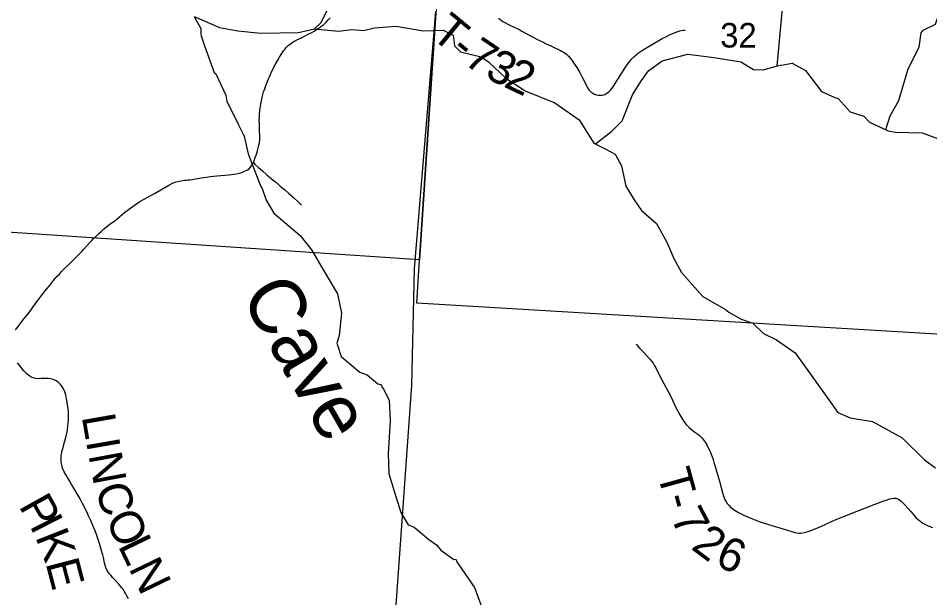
# Model space of a CAD drawing. Extents: x 396.2 to 468.4, y 232.6 to 279.1.
# Drawn here: x 414.633 to 416.187, y 271.056 to 272.044 of the extents above; entities that cross this region are included whole.
import ezdxf

# ---------------------------------------------------------------- set-up
doc = ezdxf.new("R2010")
doc.units = 0
for name, color, linetype in [('Default', 7, 'Continuous'), ('GM_X_County_Road', 7, 'Continuous'), ('GM_X_County_Road_Text', 7, 'Continuous'), ('GM_X_Minor_River', 7, 'Continuous'), ('GM_X_Minor_River_Text', 7, 'Continuous'), ('GM_X_Section', 7, 'Continuous'), ('GM_X_Section_Text', 7, 'Continuous'), ('GM_X_Township', 7, 'Continuous'), ('GM_X_Township_Road', 7, 'Continuous'), ('GM_X_Township_Road_Text', 7, 'Continuous')]:
    doc.layers.add(name, color=color, linetype=linetype)

msp = doc.modelspace()

# ---------------------------------------------------------------- linework, layer by layer
at = {"layer": 'Default'}
msp.add_lwpolyline([(414.466, 270.6401), (415.2492, 270.5871), (415.2566, 270.6906), (415.256, 270.6948), (415.2559, 270.6981), (415.2559, 270.7015), (415.2563, 270.7076), (415.2611, 270.7635), (415.2633, 270.7866), (415.2638, 270.7932), (415.2639, 270.7959), (415.264, 270.7987), (415.2639, 270.801), (415.2637, 270.8037), (415.2633, 270.8055), (415.2628, 270.8077), (415.262, 270.81), (415.2608, 270.8124), (415.3044, 271.4185), (415.3087, 271.617), (415.3585, 272.2209)], dxfattribs=at)
at = {"layer": 'GM_X_County_Road'}
for points in [[(414.6286, 271.5128), (414.6333, 271.519), (414.6378, 271.5247), (414.6434, 271.532), (414.6498, 271.5402), (414.6562, 271.5486), (414.6637, 271.5593), (414.6699, 271.5674), (414.6751, 271.5743), (414.6789, 271.5792), (414.6825, 271.5836), (414.6862, 271.5881), (414.6898, 271.5926), (414.6935, 271.597), (414.6967, 271.6007), (414.6996, 271.6041), (414.7032, 271.608), (414.7071, 271.6123), (414.7128, 271.6179), (414.7176, 271.6228), (414.7232, 271.6283), (414.7292, 271.6341), (414.7356, 271.6406), (414.7409, 271.6461), (414.745, 271.6506), (414.7493, 271.6553), (414.7551, 271.6618), (414.7585, 271.6653), (414.7619, 271.6689), (414.7657, 271.6727), (414.7698, 271.6766), (414.7744, 271.6805), (414.7787, 271.6842), (414.7893, 271.6927), (414.7981, 271.6995), (414.8141, 271.7126), (414.8249, 271.7208), (414.8328, 271.7265), (414.8407, 271.7315), (414.8538, 271.739), (414.8656, 271.7454), (414.8763, 271.7517), (414.8897, 271.7595), (414.8974, 271.7632), (414.9026, 271.7651), (414.9073, 271.7664), (414.9139, 271.7674), (414.9174, 271.7679), (414.9199, 271.7682), (414.923, 271.7684), (414.9254, 271.7686), (414.9297, 271.7692), (414.9346, 271.77), (414.9395, 271.7707), (414.9448, 271.7717), (414.95, 271.7725), (414.9541, 271.7732), (414.9603, 271.7742), (414.9662, 271.7748), (414.9719, 271.7754), (414.9784, 271.776), (414.9855, 271.7767), (414.9926, 271.7773), (415.0005, 271.7781), (415.0053, 271.7788), (415.0101, 271.7799), (415.0142, 271.7812), (415.0191, 271.7831), (415.0241, 271.7856), (415.0267, 271.7875), (415.0293, 271.7902), (415.0319, 271.7939), (415.034, 271.7978), (415.036, 271.8031), (415.0372, 271.8067), (415.0385, 271.8106), (415.0403, 271.8159), (415.0416, 271.8207), (415.0429, 271.8255), (415.0439, 271.8292), (415.0446, 271.8335), (415.045, 271.8359), (415.045, 271.8372), (415.045, 271.8402), (415.0449, 271.8432), (415.0448, 271.8458), (415.0446, 271.8502), (415.0443, 271.857), (415.0442, 271.8633), (415.044, 271.8694), (415.0442, 271.8761), (415.0444, 271.8804), (415.0451, 271.8866), (415.046, 271.8933), (415.0467, 271.8976), (415.0476, 271.903), (415.0489, 271.9091), (415.05, 271.9138), (415.0514, 271.9186), (415.0533, 271.9238), (415.0548, 271.9278), (415.0569, 271.933), (415.0583, 271.9364), (415.0599, 271.9404), (415.0614, 271.9438), (415.0631, 271.9478), (415.0651, 271.9523), (415.0678, 271.9578), (415.0703, 271.9629), (415.0723, 271.9666), (415.074, 271.9696), (415.0757, 271.9726), (415.0787, 271.9773), (415.0815, 271.9821), (415.0855, 271.9883), (415.0875, 271.9909), (415.0896, 271.9936), (415.0935, 271.9975), (415.0978, 272.0008), (415.0992, 272.0017), (415.1027, 272.004), (415.1053, 272.0054), (415.107, 272.0063), (415.1092, 272.0074), (415.1159, 272.0107), (415.1214, 272.0134), (415.1274, 272.0166), (415.1336, 272.0198), (415.1374, 272.0221), (415.1419, 272.0249), (415.1469, 272.0279), (415.1536, 272.0326), (415.1577, 272.0365), (415.1617, 272.0411), (415.1648, 272.0448)], [(414.8211, 271.0547), (414.8191, 271.0586), (414.8167, 271.063), (414.8138, 271.0677), (414.8113, 271.0713), (414.8098, 271.0733), (414.8071, 271.0766), (414.8043, 271.08), (414.7986, 271.0861), (414.794, 271.091), (414.7915, 271.094), (414.7888, 271.0971), (414.785, 271.1026), (414.7824, 271.1081), (414.7807, 271.1134), (414.7795, 271.1189), (414.7782, 271.1249), (414.7771, 271.1294), (414.7763, 271.1328), (414.7752, 271.137), (414.7717, 271.1489), (414.7689, 271.1572), (414.7664, 271.1642), (414.764, 271.1706), (414.7605, 271.1793), (414.7569, 271.1878), (414.7531, 271.1959), (414.7492, 271.2041), (414.7428, 271.2168), (414.7402, 271.2217), (414.7368, 271.2276), (414.7318, 271.2362), (414.7303, 271.2389), (414.7261, 271.2458), (414.7233, 271.2506), (414.7198, 271.2565), (414.717, 271.2613), (414.7148, 271.265), (414.7115, 271.271), (414.7088, 271.2772), (414.7072, 271.2825), (414.7063, 271.2879), (414.7061, 271.2928), (414.7064, 271.2977), (414.7076, 271.3049), (414.709, 271.3106), (414.7106, 271.3169), (414.7122, 271.3223), (414.7142, 271.3294), (414.7166, 271.3391), (414.7179, 271.3483), (414.7184, 271.3551), (414.7188, 271.3601), (414.7188, 271.3643), (414.7188, 271.3682), (414.7186, 271.3732), (414.718, 271.3784), (414.7176, 271.3825), (414.7155, 271.3954), (414.714, 271.4021), (414.7123, 271.4074), (414.7101, 271.4125), (414.7076, 271.4167), (414.7046, 271.4206), (414.701, 271.424), (414.6969, 271.4267), (414.6929, 271.4285), (414.6886, 271.4295), (414.6842, 271.43), (414.6773, 271.4299), (414.6723, 271.4297), (414.6681, 271.4296), (414.6626, 271.43), (414.6584, 271.431), (414.6551, 271.4324), (414.6521, 271.4343), (414.6483, 271.4374), (414.6427, 271.4431), (414.6387, 271.4482), (414.6318, 271.4569)]]:
    msp.add_lwpolyline(points, dxfattribs=at)
at = {"layer": 'GM_X_Minor_River'}
for points in [[(416.1121, 271.8542), (416.1199, 271.8775), (416.1347, 271.9036), (416.1503, 271.9574), (416.1692, 271.9948), (416.1726, 272.019), (416.1758, 272.0238), (416.1968, 272.0338), (416.203, 272.0503), (416.207, 272.0836), (416.2142, 272.094), (416.2338, 272.1059), (416.2645, 272.1581), (416.2738, 272.1654), (416.2944, 272.1712), (416.3238, 272.2075), (416.3467, 272.2254), (416.352, 272.2286), (416.3812, 272.2562), (416.3829, 272.2607), (416.4189, 272.288), (416.4487, 272.2996), (416.4658, 272.3021), (416.4888, 272.2998)], [(415.9271, 271.9625), (415.9384, 272.0861)], [(414.9329, 272.047), (414.9761, 272.028), (415.0073, 272.0224), (415.0465, 272.0185), (415.1112, 272.0195), (415.1382, 272.0259), (415.1495, 272.0369), (415.1652, 272.0679)], [(414.9329, 272.0471), (414.9442, 272.0266), (414.9442, 272.0183), (414.945, 272.0137), (414.9507, 271.997), (414.967, 271.9517)], [(415.1377, 272.0257), (415.1789, 272.0219), (415.2017, 272.0246), (415.222, 272.0228), (415.2403, 272.0275), (415.2775, 272.0305), (415.3233, 272.0226), (415.3574, 272.0238), (415.3749, 272.0152), (415.377, 271.9966), (415.3873, 271.9867), (415.4222, 271.978), (415.4351, 271.9696), (415.4645, 271.9417), (415.4972, 271.9202), (415.5479, 271.8996), (415.5535, 271.8956), (415.5894, 271.8705), (415.6143, 271.831), (415.634, 271.8212), (415.6507, 271.812), (415.6615, 271.7926), (415.6691, 271.7575), (415.6835, 271.7342), (415.6959, 271.7163), (415.7213, 271.6943), (415.7392, 271.6625), (415.7508, 271.6344), (415.7637, 271.6105), (415.8003, 271.5698), (415.8389, 271.5473), (415.8445, 271.543), (415.8657, 271.5313), (415.8855, 271.5242), (415.9038, 271.5065), (415.9258, 271.4959), (415.958, 271.4736), (416.015, 271.3939), (416.0306, 271.3718), (416.0515, 271.3628), (416.0894, 271.3566), (416.1404, 271.3288), (416.1782, 271.2915), (416.1971, 271.278)], [(415.6173, 271.8301), (415.6451, 271.8513), (415.6627, 271.8689), (415.6803, 271.9132), (415.6958, 271.9378), (415.7076, 271.9545), (415.7308, 271.9716), (415.7746, 271.9827), (415.8194, 271.9771), (415.8653, 271.9696), (415.8868, 271.9567), (415.9031, 271.9562), (415.9278, 271.9626), (415.9529, 271.9675), (415.9752, 271.9547), (416.0025, 271.9189), (416.0252, 271.909), (416.0309, 271.9069), (416.0513, 271.8843), (416.0746, 271.8771), (416.0844, 271.8669), (416.1165, 271.8522), (416.1289, 271.8495), (416.1746, 271.8484), (416.2348, 271.8264)], [(414.967, 271.9517), (414.97, 271.9491), (414.987, 271.9127), (414.9886, 271.9028), (415.0083, 271.8633), (415.0181, 271.8432), (415.0253, 271.8128), (415.0462, 271.7585), (415.0488, 271.7535), (415.056, 271.7341), (415.0689, 271.7117), (415.1136, 271.6734), (415.1332, 271.6492), (415.1544, 271.6135), (415.1772, 271.5744), (415.184, 271.5413), (415.1803, 271.5033), (415.1761, 271.4903), (415.1776, 271.4869), (415.1837, 271.4675), (415.2155, 271.4406), (415.228, 271.4361), (415.2461, 271.4209), (415.2522, 271.419), (415.2529, 271.4156), (415.2556, 271.4118), (415.2654, 271.3932), (415.2674, 271.3579), (415.264, 271.302), (415.2648, 271.2678), (415.2716, 271.2453), (415.2857, 271.2017), (415.2978, 271.1804), (415.3084, 271.1766), (415.333, 271.1558), (415.3462, 271.1467), (415.3534, 271.1372), (415.3757, 271.1216), (415.3791, 271.122), (415.3814, 271.1163), (415.3833, 271.1144), (415.4109, 271.0738), (415.4299, 271.0229)]]:
    msp.add_lwpolyline(points, dxfattribs=at)
at = {"layer": 'GM_X_Section'}
for points in [[(414.3535, 272.7693), (415.3883, 272.7052), (415.3792, 272.5676), (415.3171, 271.632), (414.2837, 271.7015)], [(415.3792, 272.5676), (416.3989, 272.491), (416.3419, 271.497), (415.3127, 271.5581), (415.3171, 271.632)]]:
    msp.add_lwpolyline(points, close=True, dxfattribs=at)
at = {"layer": 'GM_X_Township'}
msp.add_lwpolyline([(416.2596, 270.4764), (415.4605, 270.5176), (415.2459, 270.5284), (415.2492, 270.5871), (415.2566, 270.6906), (415.256, 270.6948), (415.2559, 270.6981), (415.2559, 270.7015), (415.2563, 270.7076), (415.2611, 270.7635), (415.2633, 270.7866), (415.2638, 270.7932), (415.2639, 270.7959), (415.264, 270.7987), (415.2639, 270.801), (415.2637, 270.8037), (415.2633, 270.8055), (415.2628, 270.8077), (415.262, 270.81), (415.2608, 270.8124), (415.3044, 271.4185), (415.3087, 271.617), (415.3585, 272.2209)], dxfattribs=at)
at = {"layer": 'GM_X_Township_Road'}
for points in [[(415.452, 272.0441), (415.4549, 272.0417), (415.457, 272.0402), (415.4596, 272.0385), (415.4637, 272.0363), (415.4692, 272.0335), (415.4809, 272.0278), (415.4864, 272.0251), (415.4919, 272.0221), (415.5075, 272.0136), (415.5196, 272.0073), (415.5268, 272.0037), (415.5335, 272.0004), (415.5413, 271.9966), (415.5479, 271.9934), (415.5545, 271.9904), (415.5575, 271.989), (415.5605, 271.9875), (415.5641, 271.9854), (415.5662, 271.984), (415.5679, 271.9826), (415.5704, 271.9803), (415.5716, 271.9791), (415.5731, 271.9773), (415.5747, 271.9755), (415.5769, 271.9726), (415.58, 271.968), (415.5853, 271.9599), (415.5905, 271.9514), (415.5943, 271.9445), (415.5974, 271.9384), (415.6031, 271.9264), (415.6047, 271.9236), (415.6063, 271.9214), (415.6081, 271.9196), (415.6105, 271.9176), (415.613, 271.916), (415.6155, 271.9147), (415.6174, 271.9139), (415.6193, 271.9133), (415.6217, 271.9129), (415.624, 271.9127), (415.6264, 271.9126), (415.6288, 271.9129), (415.6311, 271.9134), (415.6331, 271.9142), (415.6348, 271.9149), (415.6367, 271.9161), (415.6386, 271.9174), (415.6412, 271.9196), (415.6436, 271.922), (415.6459, 271.9247), (415.6483, 271.9283), (415.6546, 271.9387), (415.6615, 271.9498), (415.6684, 271.9603), (415.6742, 271.9683), (415.6791, 271.9745), (415.6826, 271.9783), (415.6864, 271.9816), (415.6905, 271.9848), (415.6956, 271.9881), (415.7062, 271.9947), (415.7184, 272.002), (415.731, 272.0091), (415.7372, 272.0124), (415.7435, 272.0154), (415.749, 272.018), (415.7534, 272.0197), (415.7577, 272.0212), (415.761, 272.0222), (415.7638, 272.0228), (415.767, 272.0234), (415.7701, 272.0237)], [(415.034, 271.7978), (415.0367, 271.7953), (415.043, 271.7895), (415.0494, 271.7837), (415.0568, 271.7773), (415.0651, 271.7705), (415.0717, 271.7649), (415.0799, 271.7579), (415.0874, 271.7513), (415.0946, 271.7453), (415.1026, 271.7382), (415.111, 271.7306), (415.1163, 271.7255)], [(415.6864, 271.4887), (415.6932, 271.4811), (415.7001, 271.4737), (415.7095, 271.4635), (415.7133, 271.459), (415.7154, 271.4561), (415.7175, 271.4529), (415.7202, 271.4479), (415.7242, 271.4397), (415.7298, 271.4291), (415.745, 271.4004), (415.7551, 271.3796), (415.7609, 271.3683), (415.7644, 271.3621), (415.7679, 271.3569), (415.7722, 271.3517), (415.7769, 271.3467), (415.7815, 271.3425), (415.7865, 271.3388), (415.7916, 271.3351), (415.7946, 271.3327), (415.7974, 271.3301), (415.7991, 271.3281), (415.801, 271.3259), (415.8044, 271.3214), (415.8077, 271.316), (415.8102, 271.3109), (415.8129, 271.3053), (415.8145, 271.3013), (415.8162, 271.2967), (415.8177, 271.2921), (415.8199, 271.285), (415.8226, 271.2762), (415.8285, 271.2553), (415.8344, 271.2334), (415.836, 271.2286), (415.8375, 271.2246), (415.8395, 271.2209), (415.842, 271.2172), (415.8447, 271.214), (415.8478, 271.2109), (415.8514, 271.2078), (415.8556, 271.205), (415.8609, 271.2019), (415.8726, 271.196), (415.8851, 271.1906), (415.8965, 271.1864), (415.9087, 271.1823), (415.9199, 271.179), (415.9319, 271.1753), (415.9443, 271.1714), (415.952, 271.169), (415.9572, 271.1676), (415.9608, 271.1669), (415.9646, 271.1666), (415.9671, 271.1666), (415.9708, 271.1671), (415.9757, 271.1681), (415.9817, 271.1699), (415.9893, 271.1727), (416.0013, 271.1779), (416.0209, 271.1866), (416.0314, 271.1912), (416.0421, 271.1955), (416.0633, 271.2038), (416.0927, 271.2152), (416.1072, 271.2207), (416.1131, 271.2227), (416.1193, 271.2248), (416.1232, 271.2257), (416.1262, 271.226), (416.128, 271.226), (416.1296, 271.2258), (416.1312, 271.2254), (416.1329, 271.2248), (416.1343, 271.2239), (416.1358, 271.223), (416.1384, 271.2208), (416.1416, 271.218), (416.1455, 271.214), (416.1552, 271.2031), (416.1643, 271.1925), (416.1679, 271.189), (416.1701, 271.1872), (416.1723, 271.1855), (416.1755, 271.1835), (416.1799, 271.1811), (416.1856, 271.1786), (416.192, 271.1763)]]:
    msp.add_lwpolyline(points, dxfattribs=at)

# ---------------------------------------------------------------- texts
at = {"layer": 'GM_X_County_Road_Text'}
for s, rotation, p in [('L', 279.8801, (414.7412, 271.3653)), ('I', 279.8807, (414.7485, 271.3234)), ('N', 280.5117, (414.7526, 271.2997)), ('C', 287.655, (414.7636, 271.2431)), ('P', 299.0998, (414.6332, 271.2128)), ('I', 297.1376, (414.6516, 271.1798)), ('O', 295.2839, (414.7808, 271.1909)), ('K', 291.5197, (414.6616, 271.1604)), ('L', 295.7181, (414.8024, 271.1453)), ('E', 284.6776, (414.6794, 271.1156)), ('N', 295.7187, (414.8208, 271.107))]:
    msp.add_text(s, height=0.0568, rotation=rotation, dxfattribs=at).set_placement(p)
at = {"layer": 'GM_X_Minor_River_Text'}
msp.add_text('Cave', height=0.09472, rotation=299.9967, dxfattribs=at).set_placement((415.0109, 271.571))
at = {"layer": 'GM_X_Section_Text'}
msp.add_text('32', height=0.04186, rotation=0, dxfattribs=at).set_placement((415.83, 271.994))
at = {"layer": 'GM_X_Township_Road_Text'}
for s, rotation, p in [('T', 320.4584, (415.3347, 272.0129)), ('-', 320.646, (415.3677, 271.9857)), ('7', 326.1617, (415.3905, 271.9674)), ('3', 333.966, (415.4269, 271.9437)), ('2', 334.5648, (415.4589, 271.928)), ('T', 285.4609, (415.7221, 271.2685)), ('-', 285.0227, (415.7334, 271.2277)), ('7', 297.8372, (415.7445, 271.1923)), ('2', 323.1675, (415.7785, 271.1406)), ('6', 336.619, (415.819, 271.1124))]:
    msp.add_text(s, height=0.0568, rotation=rotation, dxfattribs=at).set_placement(p)

doc.saveas('drawing.dxf')
